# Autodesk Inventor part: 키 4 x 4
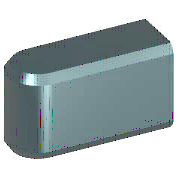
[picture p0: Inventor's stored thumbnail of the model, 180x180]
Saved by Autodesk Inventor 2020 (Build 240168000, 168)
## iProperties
Created: 2012-02
Part Number: 키 4 x 4
Material: 강철, 연강
Description: 키 및 해당 키홈
Document SubType Name: Modeling
Standard: KS B 1311
Designer: mduedu
Standards Organization: KS
Language: ko-KR
Size Designation: 4 x 4 x 18
Categories: <MemberInstance><Categories><Category DisplayName="샤프트 부품" InternalName="7f7aeb1f-a693-4053-b835-cee3144e0d98" Mnemonic="SHFT"><Category DisplayName="키" Interna
Density: 1 g/cm^3
Appearance: 주황색
IsCustomPart: 1
Author: mduedu
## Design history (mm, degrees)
sketch "스케치1"
  geometry: L1 (2, 2)-(18, 2); L2 (18, 2)-(18, -2); L3 (18, -2)-(2, -2); L4 (0, 7)-(0, -7) reference; L5 (-5, 0)-(30, 0) reference; A1 r 2 centre (2, 0) between (2, 2) and (2, -2)
  constraints: 6 end point, 3 tangent, 2 point on circle, 1 centre point, 1 horizontal, 1 parallel, 1 perpendicular, 1 point on line
  dimensions: "d0" = 2 radius of A1 (= 0.5 x PB); "d7" = 18 distance between parallel lines of L2 L4 (= NLG)
workplane "Work Plane1"
workplane "Work Plane2"
extrude "본체1" new body sketch "스케치1" taper "d3" = 0 deg; stored distance "d4" = 10
workaxis "Work Axis1"
workplane "Work Plane4"
body "Solid1"
chamfer "모따기1" distance "d8" = 0.25 (= PHH); stored, may be unused: second distance "d9" = 0.25 (= PHH), angle "d13" = 45 deg
other parameters: "d1" = -2.5 (= -PNT), "d2" = 1.5 (= PH - PNT), "NLG" = 18 [user parameter; used in 2 equation terms], "PB" = 4 [user parameter; used in 1 equation term], "PNT" = 2.5 [user parameter; used in 2 equation terms], "PH" = 4 [user parameter; used in 1 equation term], "PHH" = 0.25 [user parameter; used in 2 equation terms], "d10" = 0, "d16" = 0, "d17" = 0, "d18" = 0, "RR" = 0.08 [user parameter], "WDMAX" = 12 [user parameter], "PLB1" = 18 (= NLG) [user parameter], "PUEB" = 1.8 [user parameter]
